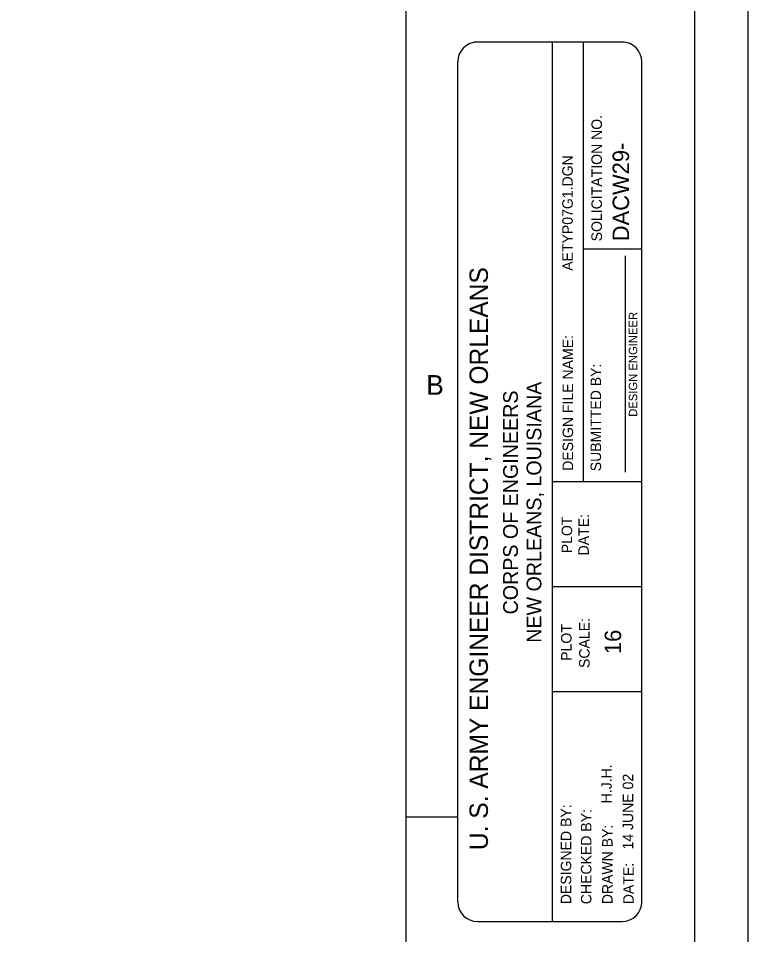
# Model space of a CAD drawing. Extents: x 22422.9 to 22498.9, y 22369.6 to 22415.
# Drawn here: x 22489.67 to 22498.93, y 22379.79 to 22391.43 of the extents above; entities that cross this region are included whole.
import ezdxf

# ---------------------------------------------------------------- set-up
doc = ezdxf.new("R2010")
doc.units = 0
for name, color, linetype in [('Level 1', 7, 'Continuous'), ('Level 10', 7, 'Continuous'), ('Level 2', 7, 'Continuous'), ('Level 7', 7, 'Continuous'), ('Level 9', 7, 'Continuous')]:
    doc.layers.add(name, color=color, linetype=linetype)

msp = doc.modelspace()

# ---------------------------------------------------------------- linework, layer by layer
at = {"layer": 'Level 1'}
for p, q in [((22497.359, 22391.125), (22495.455, 22391.125)), ((22496.447, 22391.125), (22496.447, 22379.957))]:
    msp.add_line(p, q, dxfattribs=at)
msp.add_lwpolyline([(22440.26, 22414.965), (22498.927, 22414.965), (22498.927, 22369.621), (22440.26, 22369.621)], close=True, dxfattribs=at)
for points in [[(22497.333, 22391.125), (22495.497, 22391.125)], [(22495.247, 22380.207), (22495.247, 22390.875)], [(22497.583, 22380.207), (22497.583, 22390.875)], [(22495.497, 22379.957), (22497.333, 22379.957)]]:
    msp.add_lwpolyline(points, dxfattribs=at)
for centre, start, end in [((22495.497, 22390.875), 90, 180), ((22497.333, 22390.875), 0, 90), ((22495.497, 22380.207), 180, 270), ((22497.333, 22380.207), 270, 0)]:
    msp.add_arc(centre, 0.25, start, end, dxfattribs=at)
at = {"layer": 'Level 10'}
msp.add_line((22494.591, 22381.285), (22495.247, 22381.285), dxfattribs=at)
at = {"layer": 'Level 2'}
for p, q in [((22496.84, 22391.125), (22496.84, 22385.541)), ((22497.583, 22388.496), (22496.84, 22388.496)), ((22497.375, 22385.662), (22497.375, 22388.411)), ((22497.583, 22385.541), (22496.447, 22385.541)), ((22497.583, 22384.208), (22496.447, 22384.208)), ((22497.583, 22382.875), (22496.447, 22382.875))]:
    msp.add_line(p, q, dxfattribs=at)
at = {"layer": 'Level 9'}
msp.add_line((22498.255, 22370.293), (22498.255, 22414.293), dxfattribs=at)
msp.add_lwpolyline([(22494.591, 22370.293), (22494.591, 22414.293)], dxfattribs=at)

# ---------------------------------------------------------------- texts
at = {"layer": 'Level 1'}
for s, height, p in [('SOLICITATION NO.', 0.13334, (22497.077, 22388.594)), ('AETYP07G1.DGN', 0.13334, (22496.707, 22388.22)), ('U. S. ARMY ENGINEER DISTRICT, NEW ORLEANS', 0.23333, (22495.63, 22380.863)), ('DESIGN ENGINEER', 0.10665, (22497.525, 22386.366)), ('DESIGN FILE NAME:', 0.13334, (22496.711, 22385.68)), ('SUBMITTED BY:', 0.13334, (22497.066, 22385.674)), ('PLOT', 0.1333, (22496.699, 22384.633)), ('DATE:', 0.1333, (22496.911, 22384.606)), ('PLOT', 0.1333, (22496.692, 22383.267)), ('SCALE:', 0.1333, (22496.921, 22383.176)), ('H.J.H.', 0.1333, (22497.201, 22381.457)), ('14 JUNE 02', 0.1333, (22497.474, 22380.871)), ('DESIGNED BY:', 0.13334, (22496.688, 22380.176)), ('CHECKED BY:', 0.13334, (22496.944, 22380.176)), ('DRAWN BY:', 0.1333, (22497.213, 22380.176)), ('DATE:', 0.1333, (22497.48, 22380.176))]:
    msp.add_text(s, height=height, rotation=90, dxfattribs=at).set_placement(p)
msp.add_text('B', height=0.25, dxfattribs=at).set_placement((22494.847, 22386.645))
at = {"layer": 'Level 7'}
for s, height, p in [('DACW29-', 0.208, (22497.421, 22388.595)), ('NEW ORLEANS, LOUISIANA', 0.18667, (22496.308, 22383.496)), ('CORPS OF ENGINEERS', 0.18667, (22496.01, 22383.856)), ('16', 0.208, (22497.32, 22383.352))]:
    msp.add_text(s, height=height, rotation=90, dxfattribs=at).set_placement(p)

doc.saveas('drawing.dxf')
